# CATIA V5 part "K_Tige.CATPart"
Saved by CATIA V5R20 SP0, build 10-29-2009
Part number: Tige
Bounding box of the stored display mesh (mm): x -5.174 to 494.826, y -156.303 to -128.303, z -13.976 to 13.976
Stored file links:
  G:\Khaled_CFAO_2011\ST2M\ST2M_GR2\jcoetard\Khaled\CAD_CATIA\K_Tige.CATPart
  J:\Thinkmotion\Thinkmotion_COETARD\Maquette_catia\Maquette_catia_R20_Licence_education\jcharlescoetard.CATPRODUCT\Assemblage_Pince_Prehension_Mors_Paralleles.CATProduct
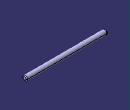
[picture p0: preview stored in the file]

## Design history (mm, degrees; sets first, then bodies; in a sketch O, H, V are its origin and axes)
External parameters (linked from other documents)
  External.Longueur_bati = 250 mm
Set1
  Line1 "Axe_tige": linked copy from another document
  Plane1 "Plan_tige": linked copy from another document
  Point1 "Point_centre_écrou": linked copy from another document
Body1 (main body)
  Sketch1 on Plane1, origin (244.8258, 0, 0), H (0, 1, 0), V (0, 0, 1)
    circle A1 centre (-142.303, 0) radius 14
    point P1 (-142.303, 0)
    reference projected point E1 (-142.303, 0) from Point1
    coincidence: P1 E1
  Pad1: profile Sketch1, direction (1, 0, 0), length 250 {= External.Longueur_bati}, mirrored extent
  Fillet1: radius 5, on face of Pad1 from Sketch1.A1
